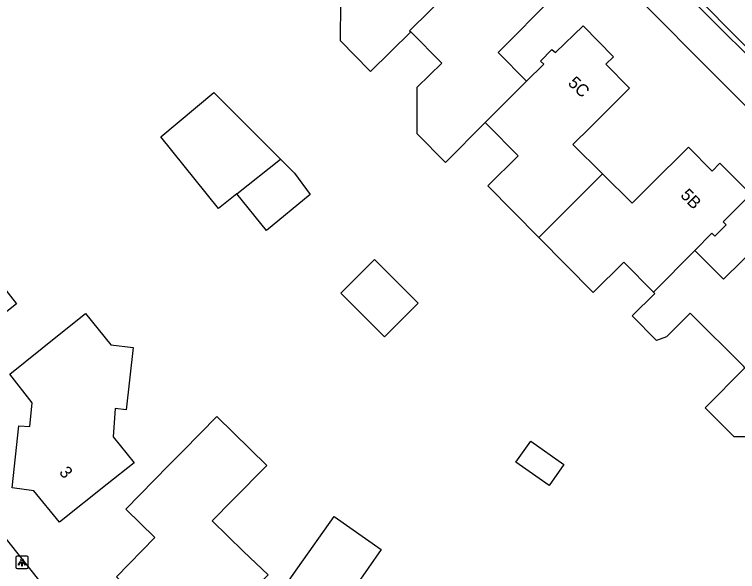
# Model space of a CAD drawing. Extents: x 159503 to 160347, y 382525 to 383272.
# Drawn here: x 160004 to 160063, y 383067.2 to 383112.7 of the extents above; entities that cross this region are included whole.
import ezdxf

# ---------------------------------------------------------------- set-up
doc = ezdxf.new("R2010")
doc.units = 0
for name, color, linetype in [('IMGEO_Lichtpunt', 7, 'Continuous'), ('IMGEO_Pand', 7, 'Continuous'), ('IMGEO_Pand_nummerreeks', 7, 'Continuous'), ('IMGEO_Rijbaan_lokaal_open', 7, 'Continuous'), ('IMGEO_Voetpad_open', 7, 'Continuous')]:
    doc.layers.add(name, color=color, linetype=linetype)

msp = doc.modelspace()

# ---------------------------------------------------------------- linework, layer by layer
at = {"layer": 'IMGEO_Lichtpunt'}
for p, q in [((160004.09, 383068.377), (160004.09, 383067.57)), ((160004.09, 383068.377), (160004.09, 383067.57)), ((160004.992, 383068.472), (160004.184, 383068.472)), ((160004.992, 383068.472), (160004.184, 383068.472)), ((160005.086, 383067.57), (160005.086, 383068.377)), ((160005.086, 383067.57), (160005.086, 383068.377)), ((160004.184, 383067.476), (160004.992, 383067.476)), ((160004.184, 383067.476), (160004.992, 383067.476))]:
    msp.add_line(p, q, dxfattribs=at)
for points in [[(160004.464, 383068.041), (160004.503, 383068.013), (160004.315, 383067.751), (160004.277, 383067.778), (160004.464, 383068.041)], [(160004.566, 383067.993), (160004.613, 383067.993), (160004.613, 383067.671), (160004.566, 383067.671), (160004.566, 383067.993)], [(160004.676, 383068.013), (160004.714, 383068.04), (160004.901, 383067.778), (160004.862, 383067.75), (160004.676, 383068.013)]]:
    msp.add_lwpolyline(points, dxfattribs=at)
msp.add_circle((160004.589, 383068.175), 0.0994, dxfattribs=at)
for centre, start, end in [((160004.184, 383068.377), 90, 180), ((160004.184, 383068.377), 90, 180), ((160004.992, 383068.377), 0, 90), ((160004.992, 383068.377), 0, 90), ((160004.184, 383067.57), 180, 270), ((160004.184, 383067.57), 180, 270), ((160004.992, 383067.57), 270, 0), ((160004.992, 383067.57), 270, 360)]:
    msp.add_arc(centre, 0.0946, start, end, dxfattribs=at)
at = {"layer": 'IMGEO_Pand'}
for points in [[(160036.311, 383111.257), (160033.044, 383108.018), (160032.964, 383108.099), (160030.58, 383110.504), (160030.598, 383113.675), (160029.836, 383113.679), (160026.442, 383117.102), (160029.132, 383119.771), (160030.062, 383118.834), (160034.833, 383123.565), (160034.577, 383123.828), (160035.504, 383124.744), (160035.763, 383124.493), (160038.003, 383126.714), (160040.531, 383124.177), (160039.901, 383123.546), (160041.817, 383121.634), (160038.641, 383118.472), (160037.215, 383117.052), (160039.586, 383114.674)], [(160039.586, 383114.674), (160040.99, 383116.079), (160040.749, 383116.34), (160041.669, 383117.242), (160041.984, 383116.966), (160044.168, 383119.245), (160046.692, 383116.707), (160046.077, 383116.072), (160047.989, 383114.149), (160043.439, 383109.554), (160045.76, 383107.219)], [(160039.586, 383114.674), (160036.228, 383111.34), (160036.311, 383111.257)], [(160042.399, 383103.856), (160039.147, 383100.602), (160036.843, 383102.926), (160036.851, 383106.723), (160038.846, 383108.701), (160036.311, 383111.257)], [(160045.76, 383107.219), (160047.17, 383108.6), (160046.917, 383108.851), (160047.844, 383109.794), (160048.12, 383109.556), (160050.377, 383111.741), (160052.869, 383109.201), (160052.229, 383108.605), (160054.178, 383106.641), (160051.002, 383103.494), (160049.558, 383102.063), (160051.976, 383099.664)], [(160042.399, 383103.856), (160045.76, 383107.219)], [(160022.131, 383098.046), (160020.621, 383096.851), (160015.912, 383102.694), (160020.255, 383106.302), (160025.683, 383100.858)], [(160046.784, 383094.465), (160042.61, 383098.674), (160045.095, 383101.138), (160042.56, 383103.694), (160042.399, 383103.856)], [(160051.976, 383099.664), (160054.378, 383097.28), (160055.82, 383098.706), (160058.986, 383101.836), (160060.914, 383099.872), (160061.53, 383100.544), (160064.06, 383098.014), (160061.817, 383095.759), (160062.063, 383095.503), (160061.144, 383094.576), (160060.877, 383094.832), (160059.496, 383093.403)], [(160025.683, 383100.858), (160025.793, 383100.748), (160026.825, 383099.713), (160028.1, 383097.98), (160024.556, 383095.037), (160022.131, 383098.046)], [(160022.131, 383098.046), (160025.683, 383100.858)], [(160051.976, 383099.664), (160046.784, 383094.465)], [(160004.152, 383089.074), (160001.451, 383086.935), (160000, 383085.786), (159997.531, 383083.83), (159996.02, 383085.698), (159995.048, 383084.943), (159991.134, 383089.869), (159995.054, 383092.974), (160000, 383096.892), (160001.098, 383097.761), (160002.775, 383095.644), (160000.423, 383093.78), (160004.152, 383089.074)], [(160059.496, 383093.403), (160061.839, 383091.063), (160066.449, 383095.597), (160068.314, 383093.763), (160068.974, 383094.338), (160071.521, 383091.806), (160069.252, 383089.609), (160069.519, 383089.3), (160068.585, 383088.376), (160068.328, 383088.622), (160066.949, 383087.227)], [(160056.126, 383090.017), (160053.701, 383092.462), (160051.215, 383089.997), (160046.784, 383094.465)], [(160056.126, 383090.017), (160059.496, 383093.403)], [(160034.162, 383086.359), (160030.598, 383089.93), (160033.35, 383092.676), (160036.913, 383089.105), (160034.162, 383086.359)], [(160063.592, 383083.846), (160063.498, 383083.939), (160059.116, 383088.311), (160057.181, 383086.372), (160056.383, 383086.067), (160054.39, 383088.076), (160056.236, 383089.906), (160056.126, 383090.017)], [(160066.949, 383087.227), (160069.292, 383084.847), (160070.721, 383086.274), (160073.877, 383089.428), (160075.773, 383087.508), (160076.427, 383088.124), (160078.97, 383085.587), (160076.725, 383083.336), (160076.98, 383083.082), (160076.062, 383082.162), (160075.808, 383082.417), (160071.062, 383077.66), (160068.507, 383080.21), (160066.509, 383078.207), (160062.713, 383078.224), (160060.35, 383080.581), (160063.592, 383083.846)], [(160011.843, 383085.728), (160013.657, 383085.494), (160013.102, 383080.419), (160012.189, 383080.526), (160012.019, 383078.201), (160013.746, 383076.102), (160011.54, 383074.345), (160007.652, 383071.248), (160005.568, 383073.804), (160003.777, 383074.045), (160004.319, 383079.118), (160005.233, 383079.064), (160005.425, 383080.99), (160003.591, 383083.329), (160007.496, 383086.453), (160009.78, 383088.28), (160011.843, 383085.728)], [(160020.124, 383071.356), (160021.809, 383073.069), (160024.568, 383075.873), (160020.5, 383079.875), (160017.742, 383077.071), (160016.56, 383075.87), (160013.053, 383072.305), (160015.426, 383069.997), (160012.296, 383066.782), (160018.479, 383060.723), (160021.981, 383064.293), (160024.677, 383066.95), (160022.671, 383068.85), (160020.124, 383071.356)], [(160047.613, 383074.239), (160044.902, 383076.154), (160046.114, 383077.869), (160048.825, 383075.954), (160047.613, 383074.239)], [(160031.769, 383065.99), (160036.505, 383062.644), (160033.333, 383058.153), (160030.448, 383054.068), (160024.953, 383057.978), (160027.292, 383061.298), (160028.107, 383062.455), (160025.273, 383064.419), (160024.441, 383063.269), (160024.22, 383063.429), (160027.105, 383067.514), (160030.074, 383071.719), (160033.905, 383069.012), (160031.769, 383065.99)]]:
    msp.add_lwpolyline(points, dxfattribs=at)
at = {"layer": 'IMGEO_Rijbaan_lokaal_open'}
msp.add_lwpolyline([(159969.339, 383112.369), (160000, 383073.962), (160006.879, 383065.344), (160051.214, 383033.728), (160053.92, 383031.798)], dxfattribs=at)
at = {"layer": 'IMGEO_Voetpad_open'}
for points in [[(160081.991, 383086.829), (160067.75, 383101.08), (160016.301, 383152.744)], [(160066.209, 383107.501), (160065.937, 383107.22), (160059.481, 383113.631), (160059.79, 383113.973)], [(160059.79, 383113.973), (160066.209, 383107.501)]]:
    msp.add_lwpolyline(points, dxfattribs=at)

# ---------------------------------------------------------------- texts
at = {"layer": 'IMGEO_Pand_nummerreeks'}
for s, rotation, p in [('5C', 315.98538, (160049.086, 383106.999)), ('5B', 314.2298, (160058.27, 383097.869)), ('3', 309.61134, (160007.57, 383075.3))]:
    msp.add_text(s, height=1, rotation=rotation, dxfattribs=at).set_placement(p)

doc.saveas('drawing.dxf')
